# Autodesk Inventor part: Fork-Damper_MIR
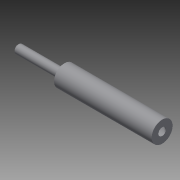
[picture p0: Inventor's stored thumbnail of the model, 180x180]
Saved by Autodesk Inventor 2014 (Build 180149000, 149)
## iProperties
Created: 2001-11
Part Number: Fork-Damper_MIR
Document SubType Name: Modeling
Designer: Autodesk, Inc.
Mass: 13.3721 g
Surface Area: 211.026 cm^2
Volume: 13.3721 cm^3
Density: 1 g/cm^3
Material: Generic
Appearance: Default
Author: Autodesk, Inc.
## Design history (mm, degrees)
derived "Fork-Damper.ipt"
body "Solid1"
tag "TaggingFeature2"
feature "DerivedBody::Fork-Damper.ipt" dims "d0" = 10
